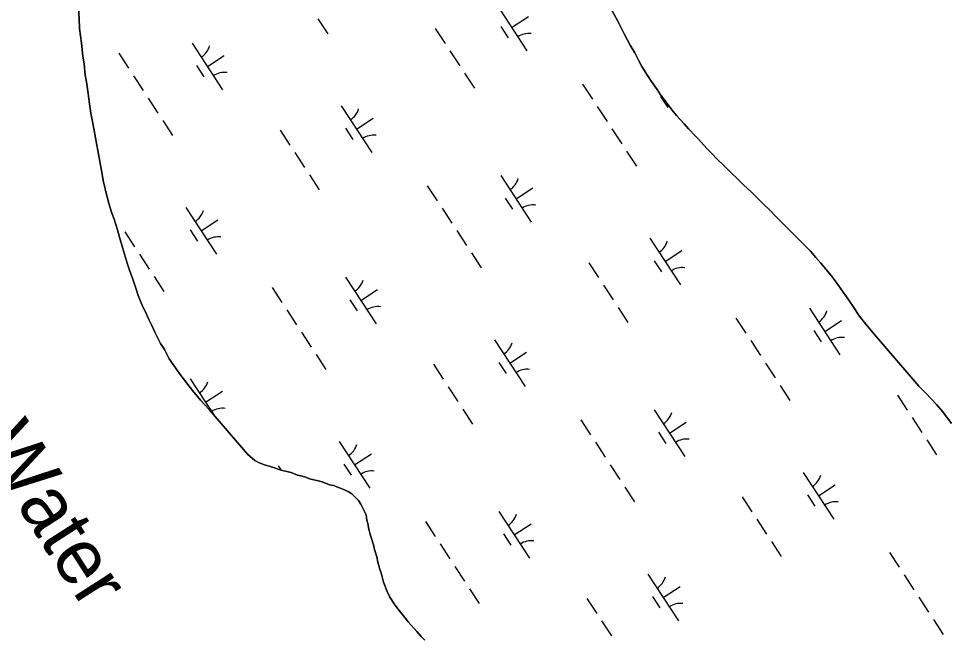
# Model space of a CAD drawing. Extents: x 3945642 to 3966284, y 206476 to 228921.
# Drawn here: x 3954297 to 3955127, y 222132 to 222689 of the extents above; entities that cross this region are included whole.
import ezdxf

# ---------------------------------------------------------------- set-up
doc = ezdxf.new("R2010")
doc.units = 0
for name, color, linetype in [('V-RIVR-IDEN', 7, 'Continuous'), ('V-TOPO-SHOR', 7, 'Continuous'), ('V-WETL-SWMP', 7, 'Continuous')]:
    doc.layers.add(name, color=color, linetype=linetype)

msp = doc.modelspace()

# ---------------------------------------------------------------- linework, layer by layer
at = {"layer": 'V-TOPO-SHOR'}
for points in [[(3954351.14, 222697.73), (3954351.52, 222688.52), (3954351.9, 222679.63), (3954353.62, 222666.48), (3954355.01, 222654.97), (3954356.04, 222648.06), (3954357.08, 222637.86), (3954358.11, 222631.95), (3954359.81, 222621.42), (3954360.51, 222614.18), (3954362.22, 222603.66), (3954363.58, 222596.43), (3954372.09, 222549.08), (3954373.11, 222543.49), (3954374.8, 222535.93), (3954376.14, 222531.01), (3954379.17, 222519.83), (3954380.85, 222514.25), (3954382.86, 222508.66), (3954385.88, 222499.13), (3954387.89, 222492.56), (3954390.58, 222483.36), (3954392.26, 222477.45), (3954394.94, 222468.25), (3954396.95, 222462.01), (3954399.29, 222455.77), (3954402.64, 222445.92), (3954404.65, 222440.33), (3954407.66, 222432.12), (3954411.66, 222424.24), (3954414, 222418.66), (3954416.32, 222414.07), (3954419.99, 222406.19), (3954424.65, 222397.33), (3954427.98, 222391.75), (3954432.3, 222383.55), (3954435.95, 222378.31), (3954441.27, 222370.77), (3954448.9, 222360.61), (3954453.21, 222355.04), (3954460.5, 222346.52), (3954468.45, 222337.68), (3954473.42, 222331.79), (3954502.58, 222298.06), (3954509.2, 222292.5), (3954512.5, 222290.55), (3954517.78, 222288.6), (3954522.72, 222286.99), (3954525.69, 222286.02), (3954530.64, 222284.4), (3954533.94, 222283.43), (3954537.89, 222282.47), (3954541.52, 222281.5), (3954547.46, 222279.23), (3954550.42, 222278.59), (3954554.71, 222277.3), (3954558.01, 222276), (3954565.92, 222274.07), (3954569.54, 222273.11), (3954576.14, 222270.51), (3954579.44, 222269.88), (3954585.04, 222267.93), (3954588.01, 222266.64), (3954592.63, 222264.68), (3954595.94, 222262.4), (3954601.9, 222256.51), (3954604.22, 222253.24), (3954607.22, 222247.33), (3954608.88, 222243.72), (3954609.57, 222238.78), (3954610.25, 222235.83), (3954611.26, 222230.89), (3954612.27, 222227.28), (3954613.28, 222223.34), (3954615.3, 222216.76), (3954616.31, 222212.49), (3954618.32, 222205.92), (3954619.33, 222201.32), (3954620.69, 222195.73), (3954622.69, 222190.48), (3954624.38, 222183.25), (3954627.72, 222175.04), (3954630.05, 222169.79), (3954634.7, 222162.9), (3954638.35, 222157.98), (3954644.65, 222150.12), (3954646.64, 222147.83)], [(3954970.91, 222516.39), (3954964.29, 222522.94), (3954958.33, 222528.83), (3954953.7, 222533.41), (3954947.41, 222539.29), (3954942.45, 222543.87), (3954935.17, 222551.07), (3954930.2, 222555.98), (3954923.25, 222562.85), (3954918.61, 222567.76), (3954914.31, 222572.01), (3954906.35, 222580.85), (3954904.04, 222583.14), (3954897.75, 222589.69), (3954893.77, 222594.27), (3954887.14, 222601.81), (3954883.17, 222606.39), (3954877.85, 222613.6), (3954872.55, 222620.15), (3954869.56, 222625.07), (3954864.58, 222632.28), (3954860.93, 222637.53), (3954855.95, 222645.73), (3954852.95, 222651.3), (3954849.62, 222657.87), (3954845.63, 222664.76), (3954839.98, 222674.93), (3954834.31, 222686.41), (3954827.99, 222698.22)], [(3955133.64, 222325.46), (3955125.68, 222335.95), (3955120.05, 222342.5), (3955110.44, 222352.64), (3955104.15, 222358.86), (3955062.73, 222407.33), (3955058.42, 222412.57), (3955055.1, 222416.5), (3955050.13, 222423.05), (3955046.47, 222428.63), (3955040.83, 222437.15), (3955036.51, 222443.38), (3955030.21, 222452.23), (3955025.56, 222458.13), (3955016.28, 222469.26), (3955011.98, 222474.51), (3955007, 222480.07), (3954999.39, 222487.93), (3954996.74, 222490.54), (3954988.46, 222498.72), (3954983.17, 222503.96), (3954975.88, 222511.49), (3954970.91, 222516.39)], [(3954646.64, 222147.83), (3954654.26, 222138.99), (3954658.24, 222134.4), (3954661.55, 222131.13)]]:
    msp.add_lwpolyline(points, dxfattribs=at)
at = {"layer": 'V-WETL-SWMP'}
for p, q in [((3954725.54, 222701.5), (3954752.94, 222659.68)), ((3954565.62, 222688.38), (3954574.39, 222674.99)), ((3954739.24, 222680.59), (3954754.3, 222690.45)), ((3954670.85, 222679.66), (3954679.62, 222666.28)), ((3954729.5, 222681.38), (3954736.08, 222671.34)), ((3954452.82, 222666.58), (3954480.22, 222624.75)), ((3954387.03, 222657.45), (3954395.79, 222644.07)), ((3954466.52, 222645.66), (3954481.58, 222655.53)), ((3954684, 222659.59), (3954692.77, 222646.2)), ((3954456.78, 222646.45), (3954463.35, 222636.42)), ((3954400.18, 222637.38), (3954408.94, 222623.99)), ((3954697.15, 222639.51), (3954705.92, 222626.13)), ((3954802.82, 222629.83), (3954811.59, 222616.45)), ((3954872.57, 222618.84), (3954879.15, 222608.8)), ((3954413.33, 222617.3), (3954422.1, 222603.92)), ((3954586.4, 222610.35), (3954613.8, 222568.53)), ((3954815.97, 222609.76), (3954824.74, 222596.38)), ((3954426.48, 222597.22), (3954435.25, 222583.84)), ((3954600.1, 222589.44), (3954615.16, 222599.3)), ((3954531.71, 222588.51), (3954540.48, 222575.13)), ((3954590.36, 222590.23), (3954596.94, 222580.19)), ((3954829.13, 222589.68), (3954837.89, 222576.3)), ((3954842.28, 222569.61), (3954851.05, 222556.22)), ((3954544.86, 222568.44), (3954553.63, 222555.05)), ((3954558.02, 222548.36), (3954566.78, 222534.98)), ((3954729.48, 222547.81), (3954756.88, 222505.98)), ((3954663.68, 222538.68), (3954672.45, 222525.3)), ((3954743.18, 222526.9), (3954758.23, 222536.76)), ((3954733.44, 222527.69), (3954740.01, 222517.65)), ((3954447.27, 222519.2), (3954474.67, 222477.37)), ((3954676.84, 222518.61), (3954685.6, 222505.22)), ((3954460.97, 222498.29), (3954476.02, 222508.15)), ((3954392.57, 222497.36), (3954401.34, 222483.98)), ((3954451.22, 222499.08), (3954457.8, 222489.04)), ((3954689.99, 222498.53), (3954698.76, 222485.15)), ((3954863.06, 222491.58), (3954890.46, 222449.76)), ((3954703.14, 222478.46), (3954711.91, 222465.07)), ((3954876.76, 222470.67), (3954891.82, 222480.53)), ((3954405.73, 222477.28), (3954414.49, 222463.9)), ((3954808.37, 222469.74), (3954817.14, 222456.36)), ((3954867.02, 222471.46), (3954873.6, 222461.42)), ((3954418.88, 222457.21), (3954427.65, 222443.83)), ((3954590.34, 222456.66), (3954617.74, 222414.83)), ((3954524.55, 222447.53), (3954533.31, 222434.15)), ((3954604.04, 222435.74), (3954619.1, 222445.61)), ((3954821.52, 222449.67), (3954830.29, 222436.28)), ((3954594.3, 222436.54), (3954600.87, 222426.5)), ((3954834.68, 222429.59), (3954843.44, 222416.21)), ((3955006.14, 222429.04), (3955033.54, 222387.22)), ((3954537.7, 222427.46), (3954546.47, 222414.07)), ((3954940.34, 222419.92), (3954949.11, 222406.53)), ((3955019.84, 222408.13), (3955034.89, 222417.99)), ((3954550.85, 222407.38), (3954559.62, 222394)), ((3955010.1, 222408.92), (3955016.67, 222398.88)), ((3954723.93, 222400.43), (3954751.32, 222358.61)), ((3954953.5, 222399.84), (3954962.26, 222386.46)), ((3954564, 222387.31), (3954572.77, 222373.92)), ((3954737.62, 222379.52), (3954752.68, 222389.38)), ((3954669.23, 222378.59), (3954678, 222365.21)), ((3954727.88, 222380.31), (3954734.46, 222370.27)), ((3954966.65, 222379.76), (3954975.41, 222366.38)), ((3954451.2, 222365.5), (3954472.83, 222332.49)), ((3954464.9, 222344.59), (3954479.96, 222354.46)), ((3954682.38, 222358.52), (3954691.15, 222345.13)), ((3954979.8, 222359.69), (3954988.57, 222346.3)), ((3955085.03, 222350.98), (3955093.8, 222337.59)), ((3954695.54, 222338.44), (3954704.3, 222325.06)), ((3954867, 222337.89), (3954894.4, 222296.06)), ((3954801.2, 222328.76), (3954809.97, 222315.38)), ((3955098.18, 222330.9), (3955106.95, 222317.52)), ((3954880.7, 222316.98), (3954895.75, 222326.84)), ((3954870.96, 222317.77), (3954877.53, 222307.73)), ((3954584.79, 222309.28), (3954612.19, 222267.45)), ((3954814.36, 222308.69), (3954823.12, 222295.3)), ((3955111.33, 222310.82), (3955120.1, 222297.44)), ((3954598.49, 222288.37), (3954613.54, 222298.23)), ((3954530.09, 222287.44), (3954532.43, 222283.87)), ((3954588.74, 222289.16), (3954595.32, 222279.12)), ((3954827.51, 222288.61), (3954836.28, 222275.23)), ((3955000.58, 222281.66), (3955027.98, 222239.84)), ((3955014.28, 222260.75), (3955029.34, 222270.61)), ((3954840.66, 222268.54), (3954849.43, 222255.15)), ((3954945.89, 222259.82), (3954954.66, 222246.44)), ((3955004.54, 222261.54), (3955011.12, 222251.5)), ((3954727.86, 222246.74), (3954755.26, 222204.91)), ((3954662.07, 222237.61), (3954670.83, 222224.23)), ((3954959.04, 222239.75), (3954967.81, 222226.37)), ((3954741.56, 222225.83), (3954756.62, 222235.69)), ((3954731.82, 222226.62), (3954738.39, 222216.58)), ((3954675.22, 222217.54), (3954683.99, 222204.15)), ((3954972.2, 222219.67), (3954980.96, 222206.29)), ((3955077.86, 222210), (3955086.63, 222196.61)), ((3954688.37, 222197.46), (3954697.14, 222184.08)), ((3954861.45, 222190.51), (3954888.85, 222148.69)), ((3955091.02, 222189.92), (3955099.78, 222176.54)), ((3954875.15, 222169.6), (3954890.2, 222179.46)), ((3954701.52, 222177.39), (3954710.29, 222164)), ((3954865.4, 222170.39), (3954871.98, 222160.35)), ((3954806.75, 222168.67), (3954815.52, 222155.29)), ((3955104.17, 222169.85), (3955112.94, 222156.46)), ((3954819.91, 222148.6), (3954828.67, 222135.21)), ((3955117.32, 222149.77), (3955126.09, 222136.39))]:
    msp.add_line(p, q, dxfattribs=at)
for points in [[(3954646.64, 222147.83), (3954644.65, 222150.12), (3954638.35, 222157.99), (3954634.7, 222162.9), (3954630.05, 222169.79), (3954627.72, 222175.04), (3954624.38, 222183.25), (3954622.69, 222190.48), (3954620.69, 222195.73), (3954619.33, 222201.32), (3954618.32, 222205.92), (3954616.31, 222212.49), (3954615.29, 222216.77), (3954613.28, 222223.34), (3954612.27, 222227.28), (3954611.26, 222230.89), (3954610.25, 222235.83), (3954609.57, 222238.78), (3954608.88, 222243.72), (3954607.22, 222247.33), (3954604.22, 222253.23), (3954601.9, 222256.51), (3954595.94, 222262.4), (3954592.63, 222264.69), (3954588.01, 222266.63), (3954585.04, 222267.93), (3954579.44, 222269.88), (3954576.14, 222270.51), (3954569.54, 222273.11), (3954565.92, 222274.07), (3954558.01, 222276), (3954554.71, 222277.3), (3954550.42, 222278.59), (3954547.46, 222279.23), (3954541.52, 222281.5), (3954537.89, 222282.47), (3954533.94, 222283.43), (3954530.64, 222284.4), (3954525.69, 222286.02), (3954522.72, 222286.99), (3954517.78, 222288.6), (3954512.5, 222290.55), (3954509.2, 222292.5), (3954502.58, 222298.06), (3954473.42, 222331.79), (3954468.45, 222337.68), (3954460.5, 222346.52), (3954453.21, 222355.04), (3954448.9, 222360.61), (3954441.27, 222370.77), (3954435.95, 222378.31), (3954432.3, 222383.55), (3954427.98, 222391.75), (3954424.65, 222397.33), (3954419.99, 222406.19), (3954416.33, 222414.07), (3954414, 222418.66), (3954411.66, 222424.24), (3954407.66, 222432.12), (3954404.65, 222440.33), (3954402.64, 222445.91), (3954399.29, 222455.77), (3954396.95, 222462.01), (3954394.94, 222468.25), (3954392.26, 222477.45), (3954390.58, 222483.36), (3954387.89, 222492.57), (3954385.88, 222499.14), (3954382.86, 222508.66), (3954380.85, 222514.25), (3954379.17, 222519.83), (3954376.14, 222531.01), (3954374.8, 222535.93), (3954373.11, 222543.49), (3954372.09, 222549.08), (3954363.58, 222596.43), (3954362.22, 222603.66), (3954360.51, 222614.18), (3954359.81, 222621.42), (3954358.11, 222631.94), (3954357.08, 222637.86), (3954356.04, 222648.06), (3954355.01, 222654.97), (3954353.62, 222666.48), (3954351.9, 222679.63), (3954351.52, 222688.52), (3954351.14, 222697.73)], [(3954827.99, 222698.23), (3954834.31, 222686.41), (3954839.98, 222674.93), (3954845.63, 222664.76), (3954849.62, 222657.87), (3954852.95, 222651.3), (3954855.95, 222645.73), (3954860.93, 222637.53), (3954864.58, 222632.28), (3954869.56, 222625.07), (3954872.55, 222620.15), (3954877.86, 222613.6), (3954883.17, 222606.39), (3954887.14, 222601.81), (3954893.77, 222594.27), (3954897.75, 222589.69), (3954904.04, 222583.14), (3954906.35, 222580.85), (3954914.31, 222572.01), (3954918.61, 222567.76), (3954923.25, 222562.85), (3954930.2, 222555.98), (3954935.16, 222551.07), (3954942.45, 222543.87), (3954947.41, 222539.29), (3954953.7, 222533.41), (3954958.33, 222528.83), (3954964.29, 222522.94), (3954970.92, 222516.39), (3954975.88, 222511.49), (3954983.17, 222503.96), (3954988.46, 222498.72), (3954996.74, 222490.54), (3954999.39, 222487.93), (3955007, 222480.07), (3955011.97, 222474.5), (3955016.28, 222469.26), (3955025.56, 222458.13), (3955030.21, 222452.23), (3955036.51, 222443.38), (3955040.83, 222437.15), (3955046.47, 222428.63), (3955050.13, 222423.05), (3955055.1, 222416.5), (3955058.42, 222412.57), (3955062.73, 222407.33), (3955104.15, 222358.86), (3955110.44, 222352.64), (3955120.05, 222342.5), (3955125.68, 222335.95), (3955133.64, 222325.46)], [(3954661.55, 222131.13), (3954658.24, 222134.4), (3954654.26, 222138.99), (3954646.64, 222147.83)]]:
    msp.add_lwpolyline(points, dxfattribs=at)
for centre, start, end in [((3954754.58, 222657.61), 82.45745, 124.00111), ((3954451.58, 222668.9), 302.45745, 344.00111), ((3954481.85, 222622.69), 82.45745, 124.00111), ((3954585.17, 222612.67), 302.45745, 344.00111), ((3954615.44, 222566.46), 82.45745, 124.00111), ((3954728.24, 222550.13), 302.45745, 344.00111), ((3954758.51, 222503.92), 82.45745, 124.00111), ((3954446.03, 222521.52), 302.45745, 344.00111), ((3954476.3, 222475.31), 82.45745, 124.00111), ((3954861.83, 222493.9), 302.45745, 344.00111), ((3954892.1, 222447.69), 82.45745, 124.00111), ((3954589.1, 222458.98), 302.45745, 344.00111), ((3954619.37, 222412.77), 82.45745, 124.00111), ((3955004.9, 222431.36), 302.45745, 344.00111), ((3955035.17, 222385.15), 82.45745, 124.00111), ((3954722.69, 222402.75), 302.45745, 344.00111), ((3954752.96, 222356.54), 82.45745, 124.00111), ((3954449.96, 222367.83), 302.45745, 344.00111), ((3954480.24, 222321.62), 82.45745, 124.00111), ((3954865.76, 222340.21), 302.45745, 344.00111), ((3954896.03, 222294), 82.45745, 124.00111), ((3954583.55, 222311.6), 302.45745, 344.00111), ((3954613.82, 222265.39), 82.45745, 124.00111), ((3954999.35, 222283.99), 302.45745, 344.00111), ((3955029.62, 222237.78), 82.45745, 124.00111), ((3954726.62, 222249.06), 302.45745, 344.00111), ((3954756.89, 222202.85), 82.45745, 124.00111), ((3954860.21, 222192.83), 302.45745, 344.00111), ((3954890.48, 222146.62), 82.45745, 124.00111)]:
    msp.add_arc(centre, 17.62, start, end, dxfattribs=at)

# ---------------------------------------------------------------- texts
at = {"layer": 'V-RIVR-IDEN'}
msp.add_text('Water', height=50, rotation=302.67566, dxfattribs=at).set_placement((3954260.95, 222306.34))

doc.saveas('drawing.dxf')
